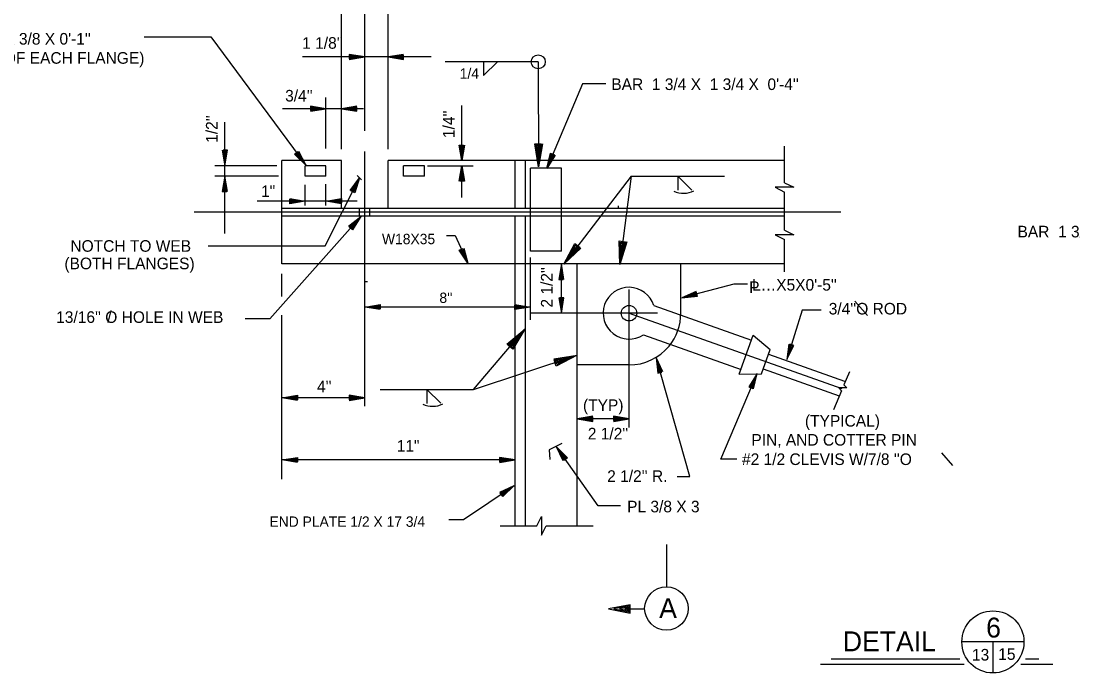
# Model space of a CAD drawing. Extents: x 0 to 13.3, y 0 to 9.3.
# Drawn here: x 5.231 to 9.463, y 5.125 to 7.75 of the extents above; entities that cross this region are included whole.
import ezdxf

# ---------------------------------------------------------------- set-up
doc = ezdxf.new("R2010")
doc.units = 0
for name, color, linetype in [('Level 13', 7, 'Continuous'), ('Level 2', 7, 'Continuous'), ('Level 25', 7, 'Continuous'), ('Level 3', 7, 'Continuous'), ('Level 50', 7, 'Continuous'), ('Level 7', 7, 'Continuous')]:
    doc.layers.add(name, color=color, linetype=linetype)

msp = doc.modelspace()

# ---------------------------------------------------------------- linework, layer by layer
at = {"layer": 'Level 13'}
for points in [[(8.3024, 7.0989), (8.3399, 7.0803), (8.2649, 7.0803), (8.3024, 7.0615)], [(8.3024, 6.9077), (8.3399, 6.8891), (8.2649, 6.8891), (8.3024, 6.8704)], [(7.3059, 5.7178), (7.3245, 5.7553), (7.3245, 5.6804), (7.3433, 5.7178)]]:
    msp.add_lwpolyline(points, dxfattribs=at)
at = {"layer": 'Level 2'}
for p, q in [((8.3024, 7.0989), (8.3024, 7.2461)), ((6.5202, 7.1884), (6.2805, 7.1884)), ((6.2805, 6.7717), (6.2805, 7.1884)), ((6.4577, 7.1675), (6.3743, 7.1675)), ((6.3743, 7.1259), (6.3743, 7.1675)), ((6.4577, 7.1259), (6.4577, 7.1675)), ((6.5202, 6.9957), (6.5202, 7.1884)), ((6.7078, 6.9957), (6.7078, 7.1884)), ((8.3024, 7.1884), (6.7078, 7.1884)), ((6.7703, 7.1259), (6.7703, 7.1675)), ((6.8537, 7.1675), (6.7703, 7.1675)), ((6.8537, 7.1259), (6.8537, 7.1675)), ((7.2185, 6.9957), (7.2185, 7.1884)), ((7.2602, 6.9957), (7.2602, 7.1884)), ((7.2805, 6.8238), (7.2805, 7.1571)), ((7.4056, 7.1571), (7.2805, 7.1571)), ((7.4056, 6.8238), (7.4056, 7.1571)), ((6.4577, 7.1259), (6.3743, 7.1259)), ((6.8537, 7.1259), (6.7703, 7.1259)), ((8.3024, 6.9077), (8.3024, 7.0615)), ((8.3024, 6.9957), (6.2805, 6.9957)), ((6.7078, 6.9957), (6.5202, 6.9957)), ((6.5932, 6.9644), (6.5932, 6.9957)), ((6.6349, 6.9644), (6.6349, 6.9957)), ((7.6352, 6.9957), (7.6352, 7.0061)), ((8.5286, 6.9801), (5.9273, 6.9801)), ((8.3024, 6.9644), (6.2805, 6.9644)), ((7.2185, 6.7717), (7.2185, 6.9644)), ((7.2602, 6.7717), (7.2602, 6.9644)), ((8.3024, 6.7399), (8.3024, 6.8704)), ((7.4056, 6.8238), (7.2805, 6.8238)), ((8.3024, 6.7717), (6.2805, 6.7717)), ((7.2185, 5.7178), (7.2185, 6.7717)), ((7.2602, 5.7178), (7.2602, 6.7717)), ((7.4685, 5.7178), (7.4685, 6.7717)), ((7.8854, 6.566), (7.8854, 6.7717)), ((7.6769, 6.113), (7.6769, 6.6691)), ((7.7764, 6.6047), (8.1693, 6.4654)), ((7.7914, 6.5736), (7.281, 6.5736)), ((7.6769, 6.5736), (8.5328, 6.2703)), ((7.8854, 6.5736), (7.8854, 6.5778)), ((7.7346, 6.4868), (8.1276, 6.3475)), ((8.1206, 6.3279), (8.1763, 6.4851)), ((8.1763, 6.4851), (8.2445, 6.4277)), ((8.2096, 6.3295), (8.2445, 6.4277)), ((8.2375, 6.4081), (8.5432, 6.2998)), ((7.6769, 6.3651), (7.4685, 6.3651)), ((8.2166, 6.3492), (8.5224, 6.2408)), ((8.1206, 6.3279), (8.2096, 6.3295)), ((8.5632, 6.3376), (8.5415, 6.2855)), ((8.5536, 6.2735), (8.5215, 6.2735)), ((8.5215, 6.2735), (8.5314, 6.2614)), ((8.5415, 6.2855), (8.5536, 6.2735)), ((8.5314, 6.2614), (8.4991, 6.1839))]:
    msp.add_line(p, q, dxfattribs=at)
msp.add_circle((7.6769, 6.5736), 0.0313, dxfattribs=at)
for radius, start, end in [(0.1042, 17.3622, 303.6132), (0.2084, 320.6443, 0), (0.2084, 270, 320.6443)]:
    msp.add_arc((7.6769, 6.5736), radius, start, end, dxfattribs=at)
at = {"layer": 'Level 25'}
for p, q in [((7.3118, 7.5856), (6.9367, 7.5856)), ((7.0921, 7.5862), (7.0921, 7.5299)), ((7.0921, 7.5299), (7.148, 7.5858)), ((7.3118, 7.5856), (7.3132, 7.1623)), ((7.3131, 7.1883), (7.3131, 7.1883)), ((7.3132, 7.1623), (7.3132, 7.1623)), ((7.6861, 7.1246), (7.4143, 6.7709)), ((7.6861, 7.1246), (7.64, 6.7701)), ((7.6861, 7.1246), (8.0612, 7.1246)), ((7.8736, 7.1246), (7.8736, 7.0683)), ((7.8736, 7.1246), (7.9296, 7.0686)), ((7.4143, 6.7709), (7.4143, 6.7709)), ((7.4301, 6.7915), (7.4301, 6.7915)), ((7.6434, 6.7958), (7.6434, 6.7958)), ((7.64, 6.7701), (7.64, 6.7701)), ((7.0512, 6.2667), (7.2579, 6.5094)), ((7.241, 6.4896), (7.241, 6.4896)), ((7.2579, 6.5094), (7.2579, 6.5094)), ((7.0512, 6.2667), (7.4683, 6.4046)), ((7.4436, 6.3965), (7.4436, 6.3965)), ((7.4683, 6.4046), (7.4683, 6.4046)), ((6.6761, 6.2667), (7.0512, 6.2667)), ((6.8636, 6.2667), (6.8636, 6.2105)), ((6.8636, 6.2667), (6.9196, 6.2108))]:
    msp.add_line(p, q, dxfattribs=at)
for points in [[(7.3284, 7.2559), (7.3132, 7.1623), (7.2974, 7.2558), (7.3239, 7.2559), (7.3131, 7.1883), (7.3024, 7.2518), (7.3194, 7.2519), (7.313, 7.2133), (7.3074, 7.2478), (7.3144, 7.2478), (7.313, 7.2393)], [(7.6675, 6.8608), (7.64, 6.7701), (7.6367, 6.8648), (7.663, 6.8614), (7.6434, 6.7958), (7.6412, 6.8602), (7.658, 6.858), (7.6466, 6.8206), (7.6456, 6.8556), (7.6525, 6.8546), (7.65, 6.8464)], [(7.4835, 6.8356), (7.4143, 6.7709), (7.459, 6.8545), (7.48, 6.8383), (7.4301, 6.7915), (7.4605, 6.8483), (7.474, 6.8379), (7.4453, 6.8114), (7.462, 6.8421), (7.4676, 6.8378), (7.4612, 6.832)], [(7.1855, 6.4483), (7.2579, 6.5094), (7.2091, 6.4282), (7.1889, 6.4454), (7.241, 6.4896), (7.2078, 6.4345), (7.1949, 6.4455), (7.2248, 6.4706), (7.2066, 6.4408), (7.2013, 6.4453), (7.208, 6.4508)], [(7.3747, 6.39), (7.4683, 6.4046), (7.3844, 6.3606), (7.3761, 6.3857), (7.4436, 6.3965), (7.3866, 6.3666), (7.3813, 6.3827), (7.4199, 6.3886), (7.3888, 6.3726), (7.3866, 6.3792), (7.3952, 6.3805)]]:
    msp.add_lwpolyline(points, dxfattribs=at)
at = {"layer": 'Level 3'}
for p, q in [((6.5202, 7.2337), (6.5202, 8.0753)), ((6.7078, 7.2337), (6.7078, 8.0657)), ((6.614, 7.3073), (6.614, 7.8609)), ((6.614, 7.6053), (6.3629, 7.6053)), ((6.5967, 7.6053), (6.5967, 7.6053)), ((6.7078, 7.6053), (6.614, 7.6053)), ((6.614, 7.6053), (6.614, 7.6053)), ((6.8813, 7.6053), (6.7078, 7.6053)), ((6.7078, 7.6053), (6.7078, 7.6053)), ((6.7252, 7.6053), (6.7252, 7.6053)), ((6.4577, 7.2369), (6.4577, 7.4417)), ((7.0042, 7.1884), (7.0042, 7.4099)), ((6.4577, 7.3968), (6.2825, 7.3968)), ((6.4403, 7.3968), (6.4403, 7.3968)), ((6.5202, 7.3968), (6.4577, 7.3968)), ((6.4577, 7.3968), (6.4577, 7.3968)), ((6.6094, 7.3968), (6.5202, 7.3968)), ((6.5202, 7.3968), (6.5202, 7.3968)), ((6.5376, 7.3968), (6.5376, 7.3968)), ((6.0512, 7.1675), (6.0512, 7.3425)), ((6.614, 6.1989), (6.614, 7.2241)), ((6.2606, 7.1675), (6.0109, 7.1675)), ((6.0512, 7.1849), (6.0512, 7.1849)), ((6.0512, 7.1057), (6.0512, 7.1675)), ((6.0512, 7.1675), (6.0512, 7.1675)), ((6.366, 7.1834), (6.366, 7.1834)), ((6.3763, 7.1695), (6.3763, 7.1695)), ((7.0042, 7.0387), (7.0042, 7.1675)), ((7.3457, 7.1567), (7.3457, 7.1567)), ((7.3525, 7.1726), (7.3525, 7.1726)), ((6.2669, 7.1259), (6.0109, 7.1259)), ((6.0512, 6.8945), (6.0512, 7.1259)), ((6.0512, 7.1259), (6.0512, 7.1259)), ((6.5928, 7.118), (6.5928, 7.118)), ((6.0512, 7.1085), (6.0512, 7.1085)), ((6.3743, 7.0073), (6.3743, 7.0898)), ((6.4577, 7.0073), (6.4577, 7.0929)), ((6.5849, 7.1025), (6.5849, 7.1025)), ((6.3743, 7.0247), (6.1804, 7.0247)), ((6.4577, 7.0247), (6.3743, 7.0247)), ((6.5837, 7.0247), (6.4577, 7.0247)), ((6.2321, 6.5509), (6.5981, 6.9631)), ((7.0216, 6.7903), (7.0216, 6.7903)), ((7.0289, 6.7746), (7.0289, 6.7746)), ((7.2805, 6.5463), (7.2805, 6.7976)), ((7.4047, 6.5736), (7.4047, 6.7717)), ((6.2805, 6.6409), (6.2805, 6.7324)), ((6.6252, 6.6994), (6.614, 6.6994)), ((7.8899, 6.636), (7.8899, 6.636)), ((7.9067, 6.6403), (7.9067, 6.6403)), ((8.5856, 6.6216), (8.6362, 6.5649)), ((6.2805, 5.9058), (6.2805, 6.5657)), ((7.2805, 6.5982), (6.614, 6.5982)), ((6.2321, 6.5509), (6.1329, 6.5509)), ((7.7855, 6.3947), (7.7855, 6.3947)), ((8.317, 6.4034), (8.317, 6.4034)), ((7.7902, 6.378), (7.7902, 6.378)), ((8.3119, 6.3869), (8.3119, 6.3869)), ((8.1861, 6.3144), (8.1861, 6.3144)), ((8.1929, 6.3303), (8.1929, 6.3303)), ((6.614, 6.2327), (6.2805, 6.2327)), ((6.5967, 6.2327), (6.5967, 6.2327)), ((6.614, 6.2327), (6.614, 6.2327)), ((7.6769, 6.1484), (7.4685, 6.1484)), ((7.4065, 6.049), (7.3552, 6.0233)), ((7.3552, 6.0233), (7.3584, 5.9849)), ((7.385, 6.036), (7.385, 6.036)), ((7.395, 6.0218), (7.395, 6.0218)), ((8.9344, 6.0109), (8.9782, 5.9602)), ((7.2185, 5.9826), (6.2805, 5.9826)), ((7.2011, 5.9826), (7.2011, 5.9826)), ((7.2185, 5.9826), (7.2185, 5.9826)), ((7.2002, 5.8697), (7.2002, 5.8697)), ((7.2145, 5.8794), (7.2145, 5.8794)), ((7.8272, 5.6424), (7.8272, 5.4703)), ((7.6814, 5.383), (7.7397, 5.383)), ((9.2657, 5.2502), (9.0157, 5.2502)), ((9.1407, 5.2502), (9.1407, 5.1252)), ((9.0072, 5.1806), (8.4902, 5.1806)), ((9.3254, 5.1806), (9.2724, 5.1806)), ((9.0256, 5.1598), (8.4472, 5.1598)), ((9.3817, 5.1598), (9.253, 5.1598))]:
    msp.add_line(p, q, dxfattribs=at)
for points in [[(5.7263, 7.6866), (5.9941, 7.6866), (6.3763, 7.1695)], [(6.5517, 7.5949), (6.614, 7.6053), (6.5517, 7.6156), (6.5517, 7.5979), (6.5967, 7.6053), (6.5543, 7.6123), (6.5543, 7.6009), (6.58, 7.6053), (6.557, 7.6089), (6.557, 7.6043), (6.5627, 7.6053)], [(6.7702, 7.6156), (6.7078, 7.6053), (6.7702, 7.5949), (6.7702, 7.6126), (6.7252, 7.6053), (6.7675, 7.5983), (6.7675, 7.6096), (6.7418, 7.6053), (6.7648, 7.6016), (6.7648, 7.6063), (6.7592, 7.6053)], [(7.5839, 7.4968), (7.4898, 7.4968), (7.3457, 7.1567)], [(6.3953, 7.3865), (6.4577, 7.3968), (6.3953, 7.4072), (6.3953, 7.3895), (6.4403, 7.3968), (6.398, 7.4038), (6.398, 7.3925), (6.4237, 7.3968), (6.4007, 7.4005), (6.4007, 7.3958), (6.4063, 7.3968)], [(6.5826, 7.4072), (6.5202, 7.3968), (6.5826, 7.3865), (6.5826, 7.4042), (6.5376, 7.3968), (6.5799, 7.3898), (6.5799, 7.4012), (6.5542, 7.3968), (6.5773, 7.3931), (6.5773, 7.3978), (6.5716, 7.3968)], [(6.0409, 7.2299), (6.0512, 7.1675), (6.0616, 7.2299), (6.0439, 7.2299), (6.0512, 7.1849), (6.0582, 7.2272), (6.0469, 7.2272), (6.0512, 7.2016), (6.0549, 7.2246), (6.0502, 7.2246), (6.0512, 7.2189)], [(6.3475, 7.2258), (6.3763, 7.1695), (6.3309, 7.2135), (6.3451, 7.224), (6.366, 7.1834), (6.3352, 7.2133), (6.3443, 7.2201), (6.3561, 7.1968), (6.3394, 7.2131), (6.3432, 7.2159), (6.3458, 7.2108)], [(7.3796, 7.21), (7.3457, 7.1567), (7.3605, 7.2181), (7.3768, 7.2112), (7.3525, 7.1726), (7.3626, 7.2143), (7.373, 7.2099), (7.359, 7.188), (7.3646, 7.2106), (7.3689, 7.2088), (7.3658, 7.2039)], [(5.9841, 6.8454), (6.4541, 6.8454), (6.5928, 7.118)], [(6.0616, 7.0635), (6.0512, 7.1259), (6.0409, 7.0635), (6.0586, 7.0635), (6.0512, 7.1085), (6.0442, 7.0662), (6.0556, 7.0662), (6.0512, 7.0918), (6.0476, 7.0688), (6.0522, 7.0688), (6.0512, 7.0745)], [(6.5553, 7.0671), (6.5928, 7.118), (6.5737, 7.0577), (6.558, 7.0658), (6.5849, 7.1025), (6.572, 7.0616), (6.5619, 7.0668), (6.5774, 7.0877), (6.5702, 7.0655), (6.5661, 7.0676), (6.5695, 7.0722)], [(6.9424, 6.886), (6.977, 6.886), (7.0289, 6.7746)], [(7.0119, 6.8355), (7.0289, 6.7746), (6.9932, 6.8268), (7.0092, 6.8342), (7.0216, 6.7903), (6.9973, 6.8258), (7.0076, 6.8305), (7.0145, 6.8054), (7.0015, 6.8247), (7.0057, 6.8267), (7.0072, 6.8212)], [(8.1529, 6.6901), (8.0989, 6.6901), (7.8899, 6.636)], [(7.9476, 6.6616), (7.8899, 6.636), (7.9528, 6.6416), (7.9484, 6.6587), (7.9067, 6.6403), (7.9494, 6.6442), (7.9466, 6.6551), (7.9228, 6.6445), (7.946, 6.6467), (7.9448, 6.6512), (7.9396, 6.6489)], [(8.4503, 6.5861), (8.3728, 6.5861), (8.3119, 6.3869)], [(8.3203, 6.4495), (8.3119, 6.3869), (8.34, 6.4435), (8.3231, 6.4486), (8.317, 6.4034), (8.3361, 6.4419), (8.3252, 6.4452), (8.3219, 6.4194), (8.3321, 6.4403), (8.3276, 6.4417), (8.3269, 6.436)], [(7.8712, 5.9162), (7.9209, 5.9162), (7.7855, 6.3947)], [(7.8124, 6.3375), (7.7855, 6.3947), (7.7925, 6.3319), (7.8095, 6.3367), (7.7902, 6.378), (7.795, 6.3354), (7.8059, 6.3385), (7.7947, 6.362), (7.7975, 6.3389), (7.802, 6.3401), (7.7995, 6.3453)], [(8.1099, 5.9858), (8.0462, 5.9858), (8.1929, 6.3303)], [(8.178, 6.2689), (8.1929, 6.3303), (8.159, 6.277), (8.1753, 6.2701), (8.1861, 6.3144), (8.1631, 6.2782), (8.1735, 6.2738), (8.1796, 6.2991), (8.1672, 6.2793), (8.1715, 6.2775), (8.1728, 6.2831)], [(6.5517, 6.2224), (6.614, 6.2327), (6.5517, 6.2431), (6.5517, 6.2254), (6.5967, 6.2327), (6.5543, 6.2397), (6.5543, 6.2284), (6.58, 6.2327), (6.557, 6.2364), (6.557, 6.2317), (6.5627, 6.2327)], [(7.6421, 5.7983), (7.5527, 5.7983), (7.385, 6.036)], [(7.4125, 5.9791), (7.385, 6.036), (7.4294, 5.991), (7.415, 5.9808), (7.395, 6.0218), (7.4251, 5.9912), (7.4159, 5.9847), (7.4046, 6.0082), (7.4209, 5.9915), (7.4171, 5.9888), (7.4146, 5.994)], [(7.1561, 5.9723), (7.2185, 5.9826), (7.1561, 5.9929), (7.1561, 5.9753), (7.2011, 5.9826), (7.1588, 5.9896), (7.1588, 5.9783), (7.1845, 5.9826), (7.1615, 5.9863), (7.1615, 5.9816), (7.1671, 5.9826)], [(6.9518, 5.7424), (7.0105, 5.7424), (7.2145, 5.8794)], [(7.157, 5.8532), (7.2145, 5.8794), (7.1686, 5.8361), (7.1587, 5.8507), (7.2002, 5.8697), (7.1689, 5.8403), (7.1626, 5.8497), (7.1863, 5.8604), (7.1693, 5.8446), (7.1667, 5.8484), (7.1719, 5.8508)], [(7.6814, 5.3952), (7.6814, 5.3996), (7.5939, 5.383), (7.6814, 5.3666), (7.6814, 5.3952), (7.6162, 5.3833), (7.6771, 5.3716), (7.6771, 5.3904), (7.6382, 5.3833), (7.6731, 5.3767), (7.6731, 5.3855), (7.6605, 5.3833), (7.6688, 5.3817)]]:
    msp.add_lwpolyline(points, dxfattribs=at)
for centre, radius in [((7.8272, 5.3847), 0.0875), ((9.1407, 5.2502), 0.125)]:
    msp.add_circle(centre, radius, dxfattribs=at)
at = {"layer": 'Level 50'}
for p, q in [((7.0042, 7.2057), (7.0042, 7.2057)), ((6.8667, 7.1675), (7.0504, 7.1675)), ((7.0042, 7.1884), (7.0042, 7.1884)), ((7.0042, 7.1675), (7.0042, 7.1675)), ((6.5832, 7.1279), (6.6013, 7.1111)), ((7.0042, 7.1502), (7.0042, 7.1502)), ((6.357, 7.0247), (6.357, 7.0247)), ((6.3743, 7.0247), (6.3743, 7.0247)), ((6.4577, 7.0247), (6.4577, 7.0247)), ((6.475, 7.0247), (6.475, 7.0247)), ((6.5866, 6.9501), (6.5866, 6.9501)), ((6.5981, 6.9631), (6.5981, 6.9631)), ((7.4047, 6.7717), (7.4047, 6.7717)), ((7.4047, 6.7544), (7.4047, 6.7544)), ((6.614, 6.5982), (6.614, 6.5982)), ((6.6314, 6.5982), (6.6314, 6.5982)), ((7.2632, 6.5982), (7.2632, 6.5982)), ((7.2805, 6.5982), (7.2805, 6.5982)), ((7.4047, 6.5909), (7.4047, 6.5909)), ((7.4047, 6.5736), (7.4047, 6.5736)), ((6.2805, 6.2327), (6.2805, 6.2327)), ((6.2979, 6.2327), (6.2979, 6.2327)), ((7.4685, 6.1484), (7.4685, 6.1484)), ((7.4858, 6.1484), (7.4858, 6.1484)), ((7.6596, 6.1484), (7.6596, 6.1484)), ((7.6769, 6.1484), (7.6769, 6.1484)), ((6.2805, 5.9826), (6.2805, 5.9826)), ((6.2979, 5.9826), (6.2979, 5.9826)), ((7.1585, 5.7178), (7.3059, 5.7178)), ((7.3433, 5.7178), (7.532, 5.7178))]:
    msp.add_line(p, q, dxfattribs=at)
for points in [[(7.0146, 7.2507), (7.0042, 7.1884), (6.9939, 7.2507), (7.0116, 7.2507), (7.0042, 7.2057), (6.9972, 7.2481), (7.0086, 7.2481), (7.0042, 7.2224), (7.0006, 7.2454), (7.0052, 7.2454), (7.0042, 7.2397)], [(6.9939, 7.1052), (7.0042, 7.1675), (7.0146, 7.1052), (6.9969, 7.1052), (7.0042, 7.1502), (7.0112, 7.1079), (6.9999, 7.1079), (7.0042, 7.1335), (7.0079, 7.1105), (7.0032, 7.1105), (7.0042, 7.1162)], [(6.312, 7.035), (6.3743, 7.0247), (6.312, 7.0143), (6.312, 7.032), (6.357, 7.0247), (6.3146, 7.0177), (6.3146, 7.029), (6.3403, 7.0247), (6.3173, 7.021), (6.3173, 7.0257), (6.323, 7.0247)], [(6.52, 7.0143), (6.4577, 7.0247), (6.52, 7.035), (6.52, 7.0173), (6.475, 7.0247), (6.5174, 7.0317), (6.5174, 7.0203), (6.4917, 7.0247), (6.5147, 7.0283), (6.5147, 7.0237), (6.509, 7.0247)], [(6.549, 6.9233), (6.5981, 6.9631), (6.5644, 6.9096), (6.5512, 6.9214), (6.5866, 6.9501), (6.5637, 6.9138), (6.5553, 6.9214), (6.5755, 6.9377), (6.563, 6.918), (6.5595, 6.9211), (6.564, 6.9247)], [(7.415, 6.7094), (7.4047, 6.7717), (7.3943, 6.7094), (7.412, 6.7094), (7.4047, 6.7544), (7.3977, 6.7121), (7.409, 6.7121), (7.4047, 6.7377), (7.401, 6.7147), (7.4057, 6.7147), (7.4047, 6.7204)], [(6.6764, 6.5879), (6.614, 6.5982), (6.6764, 6.6085), (6.6764, 6.5909), (6.6314, 6.5982), (6.6737, 6.6052), (6.6737, 6.5939), (6.648, 6.5982), (6.671, 6.6019), (6.671, 6.5972), (6.6654, 6.5982)], [(7.2182, 6.6085), (7.2805, 6.5982), (7.2182, 6.5879), (7.2182, 6.6055), (7.2632, 6.5982), (7.2209, 6.5912), (7.2209, 6.6025), (7.2465, 6.5982), (7.2235, 6.5945), (7.2235, 6.5992), (7.2292, 6.5982)], [(7.3943, 6.6359), (7.4047, 6.5736), (7.415, 6.6359), (7.3973, 6.6359), (7.4047, 6.5909), (7.4117, 6.6332), (7.4003, 6.6332), (7.4047, 6.6076), (7.4083, 6.6306), (7.4037, 6.6306), (7.4047, 6.6249)], [(6.3429, 6.2224), (6.2805, 6.2327), (6.3429, 6.2431), (6.3429, 6.2254), (6.2979, 6.2327), (6.3402, 6.2397), (6.3402, 6.2284), (6.3145, 6.2327), (6.3375, 6.2364), (6.3375, 6.2317), (6.3319, 6.2327)], [(7.5308, 6.1587), (7.4685, 6.1484), (7.5308, 6.1381), (7.5308, 6.1557), (7.4858, 6.1484), (7.5282, 6.1414), (7.5282, 6.1527), (7.5025, 6.1484), (7.5255, 6.1447), (7.5255, 6.1494), (7.5198, 6.1484)], [(7.6146, 6.1381), (7.6769, 6.1484), (7.6146, 6.1587), (7.6146, 6.1411), (7.6596, 6.1484), (7.6173, 6.1554), (7.6173, 6.1441), (7.6429, 6.1484), (7.6199, 6.1521), (7.6199, 6.1474), (7.6256, 6.1484)], [(6.3429, 5.9723), (6.2805, 5.9826), (6.3429, 5.9929), (6.3429, 5.9753), (6.2979, 5.9826), (6.3402, 5.9896), (6.3402, 5.9783), (6.3145, 5.9826), (6.3375, 5.9863), (6.3375, 5.9816), (6.3319, 5.9826)]]:
    msp.add_lwpolyline(points, dxfattribs=at)
for centre in [(7.8964, 7.1509), (6.8864, 6.293)]:
    msp.add_arc(centre, 0.0943, 245.5194, 296.0807, dxfattribs=at)
at = {"layer": 'Level 7'}
msp.add_circle((7.3118, 7.5856), 0.0281, dxfattribs=at)

# ---------------------------------------------------------------- texts
at = {"layer": 'Level 3'}
for s, height, p in [("BAR 1/2 X 3/8 X 0'-1''", 0.046688, (4.9139, 7.6549)), ("1 1/8''", 0.04669, (6.3622, 7.6381)), ('(2 ON OUTSIDE OF EACH FLANGE)', 0.04669, (4.6833, 7.5778)), ("BAR  1 3/4 X  1 3/4 X  0'-4''", 0.046688, (7.6057, 7.4721)), ("3/4''", 0.04669, (6.2936, 7.4258)), ('1" ', 0.04669, (6.1967, 7.0412)), ("BAR  1 3/4 X  1 3/4 X  0'-4''", 0.046688, (9.2396, 6.8787)), ('NOTCH TO WEB', 0.04669, (5.4297, 6.8209)), ('(BOTH FLANGES)', 0.04669, (5.4057, 6.7506)), ('P', 0.0467, (8.1601, 6.6552)), ("L…X5X0'-5''", 0.046677, (8.1718, 6.6645)), ("3/4''O ROD", 0.04667, (8.4802, 6.5684)), ("13/16'' O HOLE IN WEB", 0.04669, (5.3725, 6.5345)), ('/', 0.0467, (5.5782, 6.5356)), ("4''", 0.04669, (6.4218, 6.2556)), ('(TYP)', 0.04667, (7.4917, 6.18)), ('(TYPICAL)', 0.04667, (8.3845, 6.117)), ("2 1/2''", 0.04667, (7.5111, 6.0654)), ('11"', 0.04669, (6.7424, 6.0161)), ('PIN, AND COTTER PIN', 0.046674, (8.1691, 6.0404)), ("#2 1/2 CLEVIS W/7/8 ''O", 0.046674, (8.1315, 5.9624)), ("2 1/2'' R.", 0.04667, (7.589, 5.8945)), ('PL 3/8 X 3', 0.04669, (7.6692, 5.7718)), ('A', 0.08, (7.7982, 5.3463)), ('6', 0.08, (9.1134, 5.268)), ('DETAIL', 0.08, (8.5369, 5.2126)), ('13', 0.04679, (9.0563, 5.1752)), ('15', 0.04679, (9.162, 5.1779))]:
    msp.add_text(s, height=height, dxfattribs=at).set_placement(p)
for s, height, p in [("1/2''", 0.04669, (6.0217, 7.2596)), ("1/4''", 0.04669, (6.975, 7.2787)), ("2 1/2''", 0.04667, (7.3693, 6.5964))]:
    msp.add_text(s, height=height, rotation=90, dxfattribs=at).set_placement(p)
at = {"layer": 'Level 50'}
for s, height, p in [('1/4', 0.0417, (6.9958, 7.5176)), ('W18X35', 0.0417, (6.6831, 6.8514)), ("8''", 0.04167, (6.9142, 6.6148)), ('END PLATE 1/2 X 17 3/4', 0.041698, (6.2305, 5.7136))]:
    msp.add_text(s, height=height, dxfattribs=at).set_placement(p)

doc.saveas('drawing.dxf')
